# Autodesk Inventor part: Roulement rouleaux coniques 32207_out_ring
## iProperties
Created: 2000-12
Part Number: Roulement rouleaux coniques 32207_out_ring
Material: Par défaut
Document SubType Name: Modélisation
Designer: Administrateur
Control State: 0
Master: False
Checked Out: False
Shininess: 20.0
Length Units: 11269
Angle Units: 11279
Time Units: 11290
Mass Units: 11283
Length Display Precision: 3
Angle Display Precision: 2
Density: 0.0
Volumn: 0.0
Area: 0.0
PropertySet Name: Model Information
Author: Administrateur
